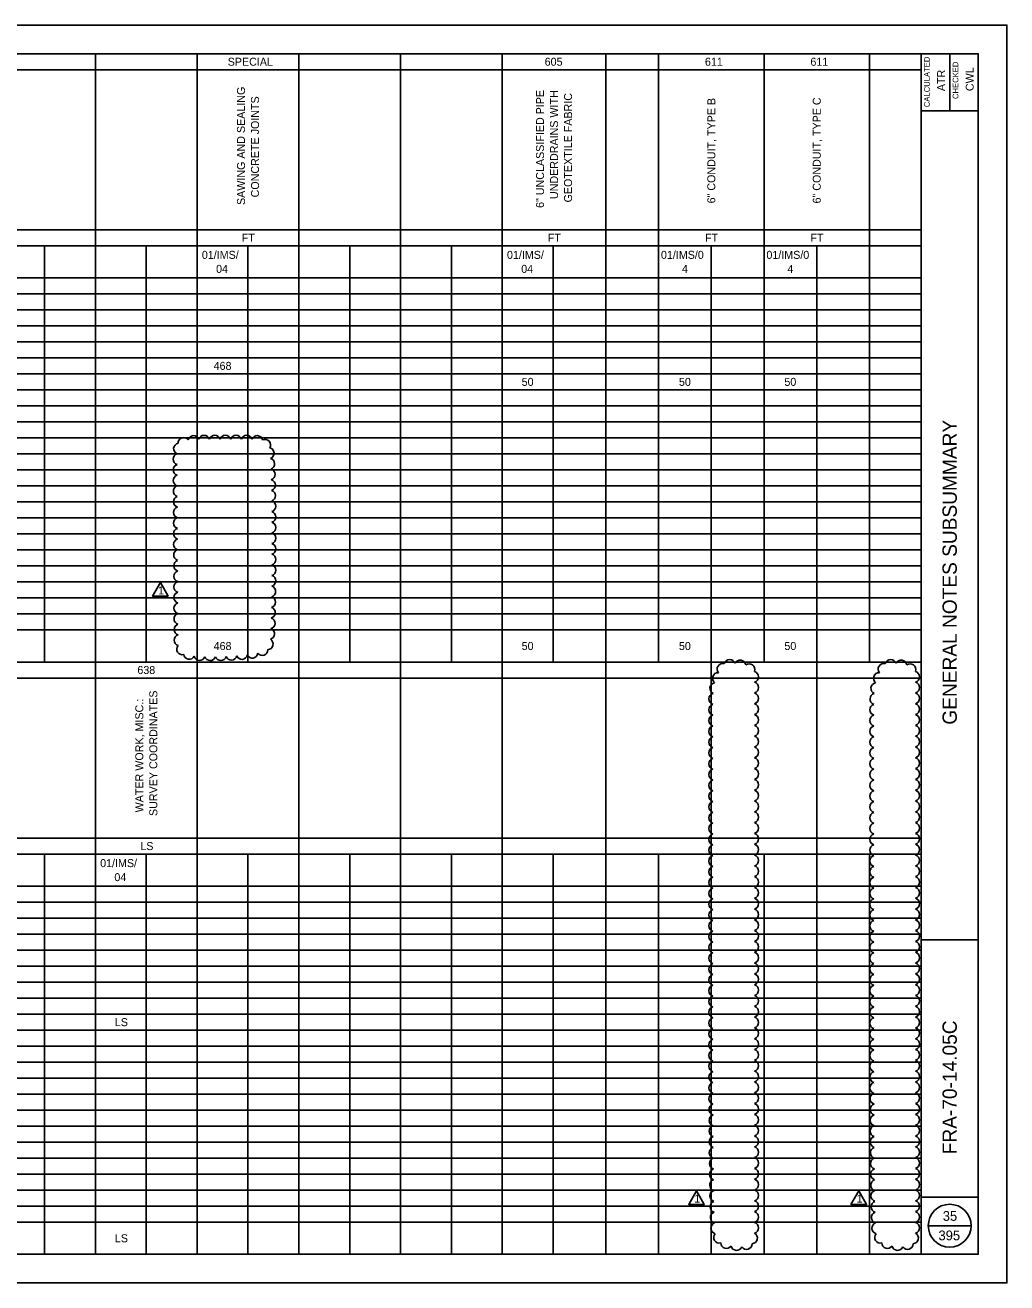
# Model space of a CAD drawing. Extents: x 0 to 34, y -2.2 to 22.
# Drawn here: x 16.83 to 34, y 0 to 22 of the extents above; entities that cross this region are included whole.
import ezdxf

# ---------------------------------------------------------------- set-up
doc = ezdxf.new("R2010")
doc.units = 0
for name, color, linetype in [('SH_Border', 7, 'Continuous'), ('SH_Cut_Line', 7, 'Continuous'), ('SH_Data', 7, 'Continuous'), ('SH_Text', 7, 'Continuous'), ('TX_P_1000', 7, 'Continuous')]:
    doc.layers.add(name, color=color, linetype=linetype)

msp = doc.modelspace()

# ---------------------------------------------------------------- linework, layer by layer
at = {"layer": 'SH_Border'}
for p, q in [((32.5, 0.5), (32.5, 21.5)), ((33, 21.5), (33, 20.5)), ((32.5, 20.5), (33.5, 20.5)), ((32.5, 6), (33.5, 6)), ((32.5, 1.5), (33.5, 1.5))]:
    msp.add_line(p, q, dxfattribs=at)
msp.add_lwpolyline([(2, 21.5), (33.5, 21.5), (33.5, 0.5), (2, 0.5)], close=True, dxfattribs=at)
at = {"layer": 'SH_Cut_Line'}
msp.add_lwpolyline([(0, 0), (34, 0), (34, 22), (0, 22)], close=True, dxfattribs=at)
at = {"layer": 'SH_Data'}
for p, q in [((2, 21.5), (32.504, 21.5)), ((18.059, 21.5), (18.059, 0.5)), ((19.838, 21.5), (19.838, 0.5)), ((21.616, 21.5), (21.616, 0.5)), ((23.395, 21.5), (23.395, 0.5)), ((25.174, 21.5), (25.174, 0.5)), ((26.986, 21.5), (26.986, 0.5)), ((27.908, 21.5), (27.908, 10.86)), ((29.753, 21.5), (29.753, 10.86)), ((31.598, 21.5), (31.598, 10.86)), ((32.504, 21.5), (32.504, 18.14)), ((5.278, 21.22), (32.504, 21.22)), ((5.278, 18.42), (32.504, 18.42)), ((2, 18.14), (32.504, 18.14)), ((17.169, 18.14), (17.169, 10.86)), ((18.948, 18.14), (18.948, 10.86)), ((20.727, 18.14), (20.727, 10.86)), ((22.506, 18.14), (22.506, 10.86)), ((24.285, 18.14), (24.285, 10.86)), ((26.064, 18.14), (26.064, 10.86)), ((28.831, 18.14), (28.831, 0.5)), ((30.675, 18.14), (30.675, 0.5)), ((32.504, 18.14), (32.504, 17.58)), ((2, 17.58), (32.504, 17.58)), ((32.504, 17.58), (32.504, 14.22)), ((2, 17.3), (32.504, 17.3)), ((2, 17.02), (32.504, 17.02)), ((2, 16.74), (32.504, 16.74)), ((2, 16.46), (32.504, 16.46)), ((2, 16.18), (32.504, 16.18)), ((2, 15.9), (32.504, 15.9)), ((2, 15.62), (32.504, 15.62)), ((2, 15.34), (32.504, 15.34)), ((2, 15.06), (32.504, 15.06)), ((2, 14.78), (32.504, 14.78)), ((2, 14.5), (32.504, 14.5)), ((2, 14.22), (32.504, 14.22)), ((32.504, 14.22), (32.504, 13.94)), ((2, 13.94), (32.504, 13.94)), ((32.504, 13.94), (32.504, 0.5)), ((2, 13.66), (32.504, 13.66)), ((2, 13.38), (32.504, 13.38)), ((2, 13.1), (32.504, 13.1)), ((2, 12.82), (32.504, 12.82)), ((2, 12.54), (32.504, 12.54)), ((2, 12.26), (32.504, 12.26)), ((2, 11.98), (32.504, 11.98)), ((2, 11.7), (32.504, 11.7)), ((2, 11.42), (32.504, 11.42)), ((2, 10.86), (32.504, 10.86)), ((5.278, 10.58), (32.504, 10.58)), ((5.278, 7.78), (32.504, 7.78)), ((2, 7.5), (32.504, 7.5)), ((17.169, 7.5), (17.169, 0.5)), ((18.948, 7.5), (18.948, 0.5)), ((20.727, 7.5), (20.727, 0.5)), ((22.506, 7.5), (22.506, 0.5)), ((24.285, 7.5), (24.285, 0.5)), ((26.064, 7.5), (26.064, 0.5)), ((27.908, 7.5), (27.908, 0.5)), ((29.753, 7.5), (29.753, 0.5)), ((31.598, 7.5), (31.598, 0.5)), ((2, 6.94), (32.504, 6.94)), ((2, 6.66), (32.504, 6.66)), ((2, 6.38), (32.504, 6.38)), ((2, 6.1), (32.504, 6.1)), ((2, 5.82), (32.504, 5.82)), ((2, 5.54), (32.504, 5.54)), ((2, 5.26), (32.504, 5.26)), ((2, 4.98), (32.504, 4.98)), ((2, 4.7), (32.504, 4.7)), ((2, 4.42), (32.504, 4.42)), ((2, 4.14), (32.504, 4.14)), ((2, 3.86), (32.504, 3.86)), ((2, 3.58), (32.504, 3.58)), ((2, 3.3), (32.504, 3.3)), ((2, 3.02), (32.504, 3.02)), ((2, 2.74), (32.504, 2.74)), ((2, 2.46), (32.504, 2.46)), ((2, 2.18), (32.504, 2.18)), ((2, 1.9), (32.504, 1.9)), ((2, 1.62), (32.504, 1.62)), ((2, 1.34), (32.504, 1.34)), ((2, 1.06), (32.504, 1.06)), ((32.625, 1), (33.375, 1)), ((5.278, 0.5), (32.504, 0.5))]:
    msp.add_line(p, q, dxfattribs=at)
msp.add_circle((33, 1), 0.375, dxfattribs=at)
at = {"layer": 'TX_P_1000'}
for points in [[(19.194, 12.249), (19.057, 12.013), (19.33, 12.013)], [(28.571, 1.608), (28.435, 1.372), (28.708, 1.372)], [(31.411, 1.608), (31.274, 1.372), (31.547, 1.372)]]:
    msp.add_lwpolyline(points, close=True, dxfattribs=at)
for centre, radius, start, end in [((19.602, 14.689), 0.0977, 36.7231, 181.7231), ((19.775, 14.722), 0.0976, 20.0252, 165.0252), ((19.96, 14.727), 0.0976, 18.0955, 163.0955), ((20.146, 14.728), 0.0976, 17.5007, 162.5007), ((20.332, 14.728), 0.0976, 17.5, 162.5), ((20.518, 14.728), 0.0976, 17.5, 162.5), ((20.704, 14.728), 0.0976, 17.4886, 162.4886), ((20.889, 14.722), 0.0976, 14.207, 159.207), ((21.023, 14.657), 0.0975, 328.8806, 113.8806), ((19.524, 14.59), 0.0975, 101.8161, 246.8161), ((21.085, 14.512), 0.0976, 292.072, 77.072), ((19.516, 14.408), 0.0976, 107.7774, 252.7774), ((19.517, 14.221), 0.0976, 107.7971, 252.7971), ((21.096, 14.327), 0.0976, 290.1112, 75.1112), ((19.518, 14.035), 0.0976, 107.805, 252.805), ((21.103, 14.141), 0.0976, 289.2389, 74.2389), ((19.519, 13.849), 0.0976, 107.8096, 252.8096), ((21.108, 13.955), 0.0976, 288.7142, 73.7142), ((21.111, 13.769), 0.0976, 288.3537, 73.3537), ((19.52, 13.663), 0.0976, 107.8127, 252.8127), ((21.114, 13.583), 0.0976, 288.0863, 73.0863), ((19.521, 13.477), 0.0976, 107.815, 252.815), ((21.115, 13.397), 0.0976, 287.8778, 72.8778), ((19.522, 13.29), 0.0976, 107.8168, 252.8168), ((21.116, 13.211), 0.0976, 287.7092, 72.7092), ((19.523, 13.104), 0.0976, 107.8182, 252.8182), ((19.524, 12.918), 0.0976, 107.8194, 252.8194), ((21.117, 13.025), 0.0976, 287.5693, 72.5693), ((19.525, 12.732), 0.0976, 107.8202, 252.8202), ((21.117, 12.839), 0.0976, 287.4584, 72.4584), ((19.526, 12.545), 0.0976, 107.8202, 252.8202), ((21.116, 12.653), 0.0976, 287.3535, 72.3535), ((21.116, 12.466), 0.0976, 287.2279, 72.2279), ((19.527, 12.359), 0.0976, 107.8202, 252.8202), ((21.115, 12.28), 0.0976, 287.0737, 72.0737), ((19.528, 12.173), 0.0976, 107.8202, 252.8202), ((21.113, 12.094), 0.0976, 286.8782, 71.8782), ((19.529, 11.987), 0.0976, 107.8202, 252.8202), ((19.53, 11.801), 0.0976, 107.8202, 252.8202), ((21.11, 11.908), 0.0976, 286.6187, 71.6187), ((19.531, 11.614), 0.0976, 107.8202, 252.8202), ((21.107, 11.722), 0.0976, 286.2502, 71.2502), ((19.532, 11.428), 0.0976, 107.8202, 252.8202), ((21.094, 11.351), 0.0976, 284.493, 69.493), ((21.102, 11.536), 0.0976, 285.6646, 70.6646), ((19.533, 11.242), 0.0976, 107.8202, 252.8202), ((21.068, 11.173), 0.0976, 273.9501, 58.9501), ((19.578, 11.085), 0.0976, 139.2641, 284.2641), ((20.803, 11.026), 0.0976, 206.7346, 351.7346), ((20.977, 11.072), 0.0977, 217.3339, 2.3339), ((19.699, 11.005), 0.0976, 188.32, 333.32), ((19.88, 10.986), 0.0976, 195.1082, 340.1082), ((20.065, 10.982), 0.0976, 197.1836, 342.1836), ((20.251, 10.983), 0.0976, 198.6029, 343.6029), ((20.436, 10.99), 0.0976, 200.3873, 345.3873), ((20.62, 11.003), 0.0976, 202.8824, 347.8824), ((29.031, 10.736), 0.099, 74.4093, 219.4093), ((29.153, 10.805), 0.0991, 19.2496, 164.2496), ((29.336, 10.794), 0.0991, 9.041, 154.041), ((29.491, 10.729), 0.099, 340.6755, 125.6755), ((31.847, 10.736), 0.099, 74.4093, 219.4093), ((31.969, 10.805), 0.0991, 19.2496, 164.2496), ((32.152, 10.794), 0.0991, 9.041, 154.041), ((32.308, 10.729), 0.099, 340.6755, 125.6755), ((28.95, 10.574), 0.0991, 87.314, 232.314), ((29.557, 10.601), 0.0992, 288.6913, 73.6913), ((31.766, 10.574), 0.0991, 87.314, 232.314), ((32.373, 10.601), 0.0992, 288.6913, 73.6913), ((28.906, 10.398), 0.0991, 99.6335, 244.6335), ((29.559, 10.413), 0.0991, 287.5, 72.5), ((31.722, 10.398), 0.0991, 99.6335, 244.6335), ((32.375, 10.413), 0.0991, 287.5, 72.5), ((28.889, 10.213), 0.0991, 105.2456, 250.2456), ((29.559, 10.224), 0.0991, 287.5, 72.5), ((29.559, 10.035), 0.0991, 287.5, 72.5), ((31.706, 10.213), 0.0991, 105.2456, 250.2456), ((32.375, 10.224), 0.0991, 287.5, 72.5), ((32.375, 10.035), 0.0991, 287.5, 72.5), ((28.886, 10.025), 0.0991, 107.4797, 252.4797), ((28.885, 9.836), 0.0991, 107.5, 252.5), ((29.559, 9.846), 0.0991, 287.5, 72.5), ((31.702, 10.025), 0.0991, 107.4797, 252.4797), ((31.702, 9.836), 0.0991, 107.5, 252.5), ((32.375, 9.846), 0.0991, 287.5, 72.5), ((28.885, 9.647), 0.0991, 107.5, 252.5), ((29.559, 9.657), 0.0991, 287.5, 72.5), ((31.702, 9.647), 0.0991, 107.5, 252.5), ((32.375, 9.657), 0.0991, 287.5, 72.5), ((28.885, 9.458), 0.0991, 107.5, 252.5), ((29.559, 9.468), 0.0991, 287.5, 72.5), ((31.702, 9.458), 0.0991, 107.5, 252.5), ((32.375, 9.468), 0.0991, 287.5, 72.5), ((28.885, 9.269), 0.0991, 107.5, 252.5), ((29.559, 9.279), 0.0991, 287.5, 72.5), ((31.702, 9.269), 0.0991, 107.5, 252.5), ((32.375, 9.279), 0.0991, 287.5, 72.5), ((28.885, 9.08), 0.0991, 107.5, 252.5), ((29.559, 9.09), 0.0991, 287.5, 72.5), ((31.702, 9.08), 0.0991, 107.5, 252.5), ((32.375, 9.09), 0.0991, 287.5, 72.5), ((28.885, 8.891), 0.0991, 107.5, 252.5), ((29.559, 8.901), 0.0991, 287.5, 72.5), ((29.559, 8.712), 0.0991, 287.5, 72.5), ((31.702, 8.891), 0.0991, 107.5, 252.5), ((32.375, 8.901), 0.0991, 287.5, 72.5), ((32.375, 8.712), 0.0991, 287.5, 72.5), ((28.885, 8.702), 0.0991, 107.5, 252.5), ((28.885, 8.513), 0.0991, 107.5, 252.5), ((29.559, 8.523), 0.0991, 287.5, 72.5), ((31.702, 8.702), 0.0991, 107.5, 252.5), ((31.702, 8.513), 0.0991, 107.5, 252.5), ((32.375, 8.523), 0.0991, 287.5, 72.5), ((28.885, 8.324), 0.0991, 107.5, 252.5), ((29.559, 8.334), 0.0991, 287.5, 72.5), ((31.702, 8.324), 0.0991, 107.5, 252.5), ((32.375, 8.334), 0.0991, 287.5, 72.5), ((28.885, 8.135), 0.0991, 107.5, 252.5), ((29.559, 8.145), 0.0991, 287.5, 72.5), ((31.702, 8.135), 0.0991, 107.5, 252.5), ((32.375, 8.145), 0.0991, 287.5, 72.5), ((28.885, 7.946), 0.0991, 107.5, 252.5), ((29.559, 7.956), 0.0991, 287.5, 72.5), ((31.702, 7.946), 0.0991, 107.5, 252.5), ((32.375, 7.956), 0.0991, 287.5, 72.5), ((28.885, 7.757), 0.0991, 107.5, 252.5), ((29.559, 7.767), 0.0991, 287.5, 72.5), ((31.702, 7.757), 0.0991, 107.5, 252.5), ((32.375, 7.767), 0.0991, 287.5, 72.5), ((28.885, 7.568), 0.0991, 107.5, 252.5), ((29.559, 7.578), 0.0991, 287.5, 72.5), ((29.559, 7.389), 0.0991, 287.5, 72.5), ((31.702, 7.568), 0.0991, 107.5, 252.5), ((32.375, 7.578), 0.0991, 287.5, 72.5), ((32.375, 7.389), 0.0991, 287.5, 72.5), ((28.885, 7.379), 0.0991, 107.5, 252.5), ((28.885, 7.19), 0.0991, 107.5, 252.5), ((29.559, 7.2), 0.0991, 287.5, 72.5), ((31.702, 7.379), 0.0991, 107.5, 252.5), ((31.702, 7.19), 0.0991, 107.5, 252.5), ((32.375, 7.2), 0.0991, 287.5, 72.5), ((28.885, 7.001), 0.0991, 107.5, 252.5), ((29.559, 7.011), 0.0991, 287.5, 72.5), ((31.702, 7.001), 0.0991, 107.5, 252.5), ((32.375, 7.011), 0.0991, 287.5, 72.5), ((28.885, 6.812), 0.0991, 107.5, 252.5), ((29.559, 6.822), 0.0991, 287.5, 72.5), ((31.702, 6.812), 0.0991, 107.5, 252.5), ((32.375, 6.822), 0.0991, 287.5, 72.5), ((28.885, 6.623), 0.0991, 107.5, 252.5), ((29.559, 6.633), 0.0991, 287.5, 72.5), ((31.702, 6.623), 0.0991, 107.5, 252.5), ((32.375, 6.633), 0.0991, 287.5, 72.5), ((28.885, 6.434), 0.0991, 107.5, 252.5), ((29.559, 6.444), 0.0991, 287.5, 72.5), ((31.702, 6.434), 0.0991, 107.5, 252.5), ((32.375, 6.444), 0.0991, 287.5, 72.5), ((28.885, 6.245), 0.0991, 107.5, 252.5), ((29.559, 6.255), 0.0991, 287.5, 72.5), ((29.559, 6.066), 0.0991, 287.5, 72.5), ((31.702, 6.245), 0.0991, 107.5, 252.5), ((32.375, 6.255), 0.0991, 287.5, 72.5), ((32.375, 6.066), 0.0991, 287.5, 72.5), ((28.885, 6.056), 0.0991, 107.5, 252.5), ((28.885, 5.867), 0.0991, 107.5, 252.5), ((29.559, 5.877), 0.0991, 287.5, 72.5), ((31.702, 6.056), 0.0991, 107.5, 252.5), ((31.702, 5.867), 0.0991, 107.5, 252.5), ((32.375, 5.877), 0.0991, 287.5, 72.5), ((28.885, 5.678), 0.0991, 107.5, 252.5), ((29.559, 5.688), 0.0991, 287.5, 72.5), ((31.702, 5.678), 0.0991, 107.5, 252.5), ((32.375, 5.688), 0.0991, 287.5, 72.5), ((28.885, 5.489), 0.0991, 107.5, 252.5), ((29.559, 5.499), 0.0991, 287.5, 72.5), ((31.702, 5.489), 0.0991, 107.5, 252.5), ((32.375, 5.499), 0.0991, 287.5, 72.5), ((28.885, 5.3), 0.0991, 107.5, 252.5), ((29.559, 5.31), 0.0991, 287.5, 72.5), ((31.702, 5.3), 0.0991, 107.5, 252.5), ((32.375, 5.31), 0.0991, 287.5, 72.5), ((28.886, 5.111), 0.0991, 107.5091, 252.5091), ((29.559, 5.121), 0.0991, 287.5, 72.5), ((31.702, 5.111), 0.0991, 107.5091, 252.5091), ((32.375, 5.121), 0.0991, 287.5, 72.5), ((28.886, 4.922), 0.0991, 107.5258, 252.5258), ((29.559, 4.932), 0.0991, 287.5, 72.5), ((31.702, 4.922), 0.0991, 107.5258, 252.5258), ((32.375, 4.932), 0.0991, 287.5, 72.5), ((28.886, 4.733), 0.0991, 107.5437, 252.5437), ((28.886, 4.544), 0.0991, 107.5629, 252.5629), ((29.559, 4.743), 0.0991, 287.5, 72.5), ((29.559, 4.554), 0.0991, 287.5, 72.5), ((31.702, 4.733), 0.0991, 107.5437, 252.5437), ((31.702, 4.544), 0.0991, 107.5629, 252.5629), ((32.375, 4.743), 0.0991, 287.5, 72.5), ((32.375, 4.554), 0.0991, 287.5, 72.5), ((28.886, 4.355), 0.0991, 107.5836, 252.5836), ((29.559, 4.365), 0.0991, 287.5, 72.5), ((31.703, 4.355), 0.0991, 107.5836, 252.5836), ((32.375, 4.365), 0.0991, 287.5, 72.5), ((28.886, 4.166), 0.0991, 107.606, 252.606), ((29.559, 4.176), 0.0991, 287.5, 72.5), ((31.703, 4.166), 0.0991, 107.606, 252.606), ((32.375, 4.176), 0.0991, 287.5, 72.5), ((28.887, 3.977), 0.0991, 107.6303, 252.6303), ((29.559, 3.987), 0.0991, 287.5, 72.5), ((31.703, 3.977), 0.0991, 107.6303, 252.6303), ((32.375, 3.987), 0.0991, 287.5, 72.5), ((28.887, 3.788), 0.0991, 107.6568, 252.6568), ((29.559, 3.797), 0.0991, 287.5, 72.5), ((31.704, 3.788), 0.0991, 107.6568, 252.6568), ((32.375, 3.797), 0.0991, 287.5, 72.5), ((28.888, 3.599), 0.0991, 107.6859, 252.6859), ((29.559, 3.608), 0.0991, 287.5, 72.5), ((31.704, 3.599), 0.0991, 107.6859, 252.6859), ((32.375, 3.608), 0.0991, 287.5, 72.5), ((28.889, 3.41), 0.0991, 107.718, 252.718), ((28.889, 3.221), 0.0991, 107.7537, 252.7537), ((29.559, 3.419), 0.0991, 287.5, 72.5), ((29.559, 3.23), 0.0991, 287.5, 72.5), ((31.705, 3.41), 0.0991, 107.718, 252.718), ((31.706, 3.221), 0.0991, 107.7537, 252.7537), ((32.375, 3.419), 0.0991, 287.5, 72.5), ((32.375, 3.23), 0.0991, 287.5, 72.5), ((28.89, 3.032), 0.0991, 107.7938, 252.7938), ((29.559, 3.041), 0.0991, 287.5, 72.5), ((31.707, 3.032), 0.0991, 107.7938, 252.7938), ((32.375, 3.041), 0.0991, 287.5, 72.5), ((28.891, 2.843), 0.0991, 107.8391, 252.8391), ((29.559, 2.852), 0.0991, 287.5, 72.5), ((31.708, 2.843), 0.0991, 107.8391, 252.8391), ((32.375, 2.852), 0.0991, 287.5, 72.5), ((28.892, 2.654), 0.0991, 107.8909, 252.8909), ((29.559, 2.663), 0.0991, 287.5, 72.5), ((31.709, 2.654), 0.0991, 107.8909, 252.8909), ((32.375, 2.663), 0.0991, 287.5, 72.5), ((28.894, 2.465), 0.0991, 107.951, 252.951), ((29.559, 2.474), 0.0991, 287.5, 72.5), ((31.71, 2.465), 0.0991, 107.951, 252.951), ((32.375, 2.474), 0.0991, 287.5, 72.5), ((28.895, 2.276), 0.0991, 108.0219, 253.0219), ((29.559, 2.285), 0.0991, 287.5, 72.5), ((31.712, 2.276), 0.0991, 108.0219, 253.0219), ((32.375, 2.285), 0.0991, 287.5, 72.5), ((28.897, 2.087), 0.0991, 108.1071, 253.1071), ((28.899, 1.898), 0.0991, 108.2123, 253.2123), ((29.559, 2.096), 0.0991, 287.5, 72.5), ((29.559, 1.907), 0.0991, 287.5, 72.5), ((31.714, 2.087), 0.0991, 108.1071, 253.1071), ((31.716, 1.898), 0.0991, 108.2123, 253.2123), ((32.375, 2.096), 0.0991, 287.5, 72.5), ((32.375, 1.907), 0.0991, 287.5, 72.5), ((28.902, 1.709), 0.0991, 108.3469, 253.3469), ((29.559, 1.718), 0.0991, 287.5, 72.5), ((31.719, 1.709), 0.0991, 108.3469, 253.3469), ((32.375, 1.718), 0.0991, 287.5, 72.5), ((28.905, 1.521), 0.0991, 108.5276, 253.5276), ((29.559, 1.529), 0.0991, 287.5, 72.5), ((31.722, 1.521), 0.0991, 108.5276, 253.5276), ((32.375, 1.529), 0.0991, 287.5, 72.5), ((28.909, 1.332), 0.0991, 108.7891, 253.7891), ((29.559, 1.34), 0.0991, 287.5, 72.5), ((31.725, 1.332), 0.0991, 108.7891, 253.7891), ((32.375, 1.34), 0.0991, 287.5, 72.5), ((28.914, 1.143), 0.0991, 109.2189, 254.2189), ((29.559, 1.151), 0.0991, 287.5, 72.5), ((31.73, 1.143), 0.0991, 109.2189, 254.2189), ((32.375, 1.151), 0.0991, 287.5, 72.5), ((28.921, 0.955), 0.0991, 110.1571, 255.1571), ((29.559, 0.962), 0.0991, 287.5, 72.5), ((31.738, 0.955), 0.0991, 110.1571, 255.1571), ((32.375, 0.962), 0.0991, 287.5, 72.5), ((28.971, 0.794), 0.0991, 139.2663, 284.2663), ((29.094, 0.7), 0.0991, 180.783, 325.783), ((29.446, 0.685), 0.0991, 214.5703, 359.5703), ((29.538, 0.783), 0.0991, 274.2898, 59.2898), ((31.787, 0.794), 0.0991, 139.2663, 284.2663), ((31.911, 0.7), 0.0991, 180.783, 325.783), ((32.263, 0.685), 0.0991, 214.5703, 359.5703), ((32.354, 0.783), 0.0991, 274.2898, 59.2898), ((29.273, 0.666), 0.0991, 192.8167, 337.8167), ((32.089, 0.666), 0.0991, 192.8167, 337.8167)]:
    msp.add_arc(centre, radius, start, end, dxfattribs=at)

# ---------------------------------------------------------------- texts
at = {"layer": 'SH_Data'}
for s, height, p in [('CALCULATED', 0.1, (32.652, 20.565)), ('CHECKED', 0.1, (33.152, 20.708)), ('ATR', 0.14, (32.92, 20.846)), ('CWL', 0.14, (33.42, 20.846)), ('GENERAL NOTES SUBSUMMARY', 0.25, (33.125, 9.764)), ('FRA-70-14.05C', 0.25, (33.125, 2.249))]:
    msp.add_text(s, height=height, rotation=90, dxfattribs=at).set_placement(p)
at = {"layer": 'SH_Text'}
for s, height, p in [('SPECIAL', 0.14, (20.372, 21.29)), ('605', 0.14, (25.916, 21.29)), ('611', 0.14, (28.719, 21.29)), ('611', 0.14, (30.564, 21.29)), ('FT', 0.14, (20.617, 18.21)), ('FT', 0.14, (25.97, 18.21)), ('FT', 0.14, (28.72, 18.21)), ('FT', 0.14, (30.565, 18.21)), ('01/IMS/', 0.14, (19.92, 17.912)), ('01/IMS/', 0.14, (25.257, 17.912)), ('01/IMS/0', 0.14, (27.95, 17.912)), ('01/IMS/0', 0.14, (29.795, 17.912)), ('04', 0.14, (20.169, 17.667)), ('04', 0.14, (25.506, 17.667)), ('4', 0.14, (28.317, 17.667)), ('4', 0.14, (30.162, 17.667)), ('468', 0.14, (20.126, 15.97)), ('50', 0.14, (25.514, 15.69)), ('50', 0.14, (28.265, 15.69)), ('50', 0.14, (30.109, 15.69)), ('468', 0.14, (20.126, 11.07)), ('50', 0.14, (25.514, 11.07)), ('50', 0.14, (28.265, 11.07)), ('50', 0.14, (30.109, 11.07)), ('638', 0.14, (18.792, 10.65)), ('LS', 0.14, (18.844, 7.57)), ('01/IMS/', 0.14, (18.141, 7.272)), ('04', 0.14, (18.39, 7.027)), ('LS', 0.14, (18.399, 4.49)), ('35', 0.17, (32.879, 1.085)), ('395', 0.17, (32.804, 0.745)), ('LS', 0.14, (18.399, 0.71))]:
    msp.add_text(s, height=height, dxfattribs=at).set_placement(p)
for s, p in [('SAWING AND SEALING', (20.675, 18.854)), ('CONCRETE JOINTS', (20.92, 18.987)), ('6" UNCLASSIFIED PIPE', (25.905, 18.803)), ('UNDERDRAINS WITH', (26.15, 18.958)), ('GEOTEXTILE FABRIC', (26.395, 18.899)), ('6" CONDUIT, TYPE B', (28.901, 18.882)), ('6" CONDUIT, TYPE C', (30.745, 18.881)), ('SURVEY COORDINATES', (19.141, 8.166)), ('WATER WORK, MISC.:', (18.896, 8.23))]:
    msp.add_text(s, height=0.14, rotation=90, dxfattribs=at).set_placement(p)
at = {"layer": 'TX_P_1000'}
for p in [(19.155, 12.043), (28.532, 1.403), (31.372, 1.403)]:
    msp.add_text('1', height=0.14, rotation=360, dxfattribs=at).set_placement(p)

doc.saveas('drawing.dxf')
